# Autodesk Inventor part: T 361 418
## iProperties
Company: Mayer & Müller AG Schaltgeräte
Shininess: 64.0
Length Units: 11269
Angle Units: 11279
Time Units: 11290
Mass Units: 11283
Length Display Precision: 3
Angle Display Precision: 2
Compacted: True
Part Number: T 361 418
Document SubType Name: Modeling
Created: 2006-10
Material: 2.0380.26
Designer: cad4
Manufacturer: Standard
Standards Organization: Custom
Description: Lagerblech
Density: 8.2 g/cm^3
Density: 0.0
Volumn: 0.0
Area: 0.0
PropertySet Name: Model Information
Control State: 0
Master: False
Checked Out: False
Zweck: für Isolator
Abmessung: Fl. 45x4
HalbzeugNorm: DIN 1759
Keywords: 382129
Revision Number: 361418
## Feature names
1. Extrusion1
2. Extrusion2
3. Extrusion3
